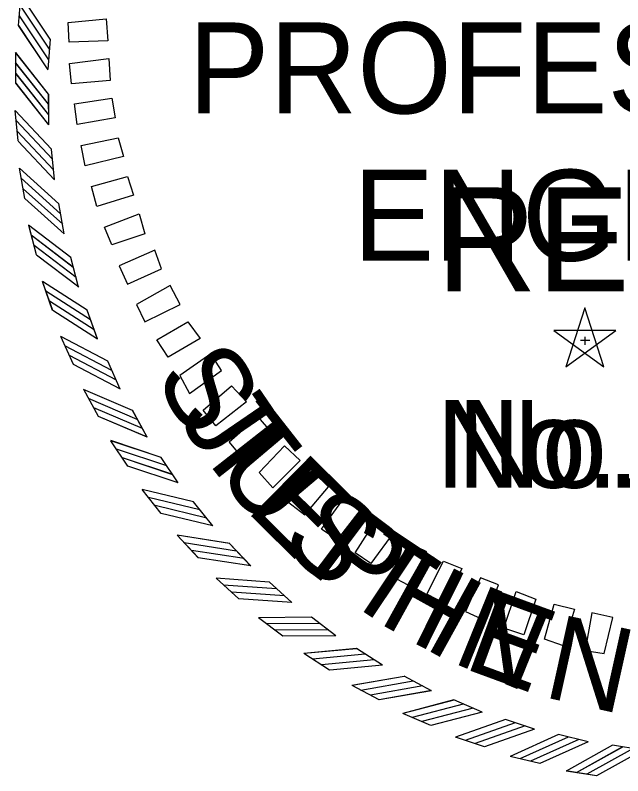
# Model space of a CAD drawing. Extents: x 16 to 1228740, y 11 to 152440.
# Drawn here: x 17.6793 to 17.754, y 10.8162 to 10.9098 of the extents above; entities that cross this region are included whole.
import ezdxf

# ---------------------------------------------------------------- set-up
doc = ezdxf.new("R2010")
doc.units = 0
for name, color, linetype in [('STAMP_FRED', 7, 'Continuous'), ('STAMP_JUSTIN', 7, 'Continuous'), ('STAMP_PRELIM', 7, 'Continuous')]:
    doc.layers.add(name, color=color, linetype=linetype)

msp = doc.modelspace()

# ---------------------------------------------------------------- linework, layer by layer
at = {"layer": 'STAMP_FRED'}
for p, q in [((17.6797, 10.908524), (17.679977, 10.912284)), ((17.683323, 10.903099), (17.683601, 10.906868)), ((17.67937, 10.901425), (17.679335, 10.905195)), ((17.683429, 10.896318), (17.683394, 10.900096)), ((17.679627, 10.894324), (17.679282, 10.898078)), ((17.684094, 10.889569), (17.683748, 10.893331)), ((17.680471, 10.887267), (17.679816, 10.89098)), ((17.685315, 10.882897), (17.684658, 10.886619)), ((17.681893, 10.880305), (17.680934, 10.883951)), ((17.687082, 10.87635), (17.686121, 10.880004)), ((17.683886, 10.873483), (17.682629, 10.877038)), ((17.749354, 10.873788), (17.746995, 10.866552)), ((17.751704, 10.866556), (17.749359, 10.873797)), ((17.689384, 10.86997), (17.688124, 10.873533)), ((17.753156, 10.871026), (17.745545, 10.871033)), ((17.745552, 10.871026), (17.751705, 10.866547)), ((17.747004, 10.866556), (17.753165, 10.871024)), ((17.686436, 10.86685), (17.68489, 10.870288)), ((17.749361, 10.870216), (17.749361, 10.869262)), ((17.748812, 10.86981), (17.749943, 10.86981)), ((17.692204, 10.863803), (17.690655, 10.867249)), ((17.689524, 10.86045), (17.6877, 10.863749)), ((17.695525, 10.857889), (17.693696, 10.861196)), ((17.693131, 10.854326), (17.69104, 10.857463)), ((17.699322, 10.85227), (17.697227, 10.855415)), ((17.697231, 10.848522), (17.694888, 10.851475)), ((17.703571, 10.846984), (17.701223, 10.849945)), ((17.701796, 10.843075), (17.699217, 10.845825)), ((17.708241, 10.842067), (17.705657, 10.844823)), ((17.706795, 10.838025), (17.703998, 10.840552)), ((17.713302, 10.837552), (17.710498, 10.840085)), ((17.712195, 10.833404), (17.709198, 10.835692)), ((17.718718, 10.83347), (17.715715, 10.835764)), ((17.724453, 10.82985), (17.721271, 10.831887)), ((17.717957, 10.829245), (17.714782, 10.831278)), ((17.730467, 10.826715), (17.727127, 10.828483)), ((17.724043, 10.825577), (17.720711, 10.82734)), ((17.736719, 10.824088), (17.733245, 10.825574)), ((17.730412, 10.822423), (17.726946, 10.823905)), ((17.743167, 10.821986), (17.739582, 10.82318)), ((17.749767, 10.820424), (17.746096, 10.821318)), ((17.737019, 10.819806), (17.733442, 10.820997)), ((17.756473, 10.819412), (17.75274, 10.82)), ((17.743819, 10.817743), (17.740156, 10.818635)), ((17.750767, 10.81625), (17.747043, 10.816836))]:
    msp.add_line(p, q, dxfattribs=at)
for points in [[(17.683598, 10.906863), (17.679974, 10.912288)], [(17.683494, 10.905612), (17.679871, 10.911036)], [(17.683427, 10.904304), (17.679803, 10.909728)], [(17.683326, 10.903094), (17.679703, 10.908519)], [(17.683392, 10.900092), (17.679333, 10.905199)], [(17.683392, 10.898836), (17.679333, 10.903943)], [(17.683433, 10.897527), (17.679374, 10.902633)], [(17.683433, 10.896313), (17.679374, 10.90142)], [(17.683745, 10.893327), (17.679279, 10.898081)], [(17.683849, 10.892075), (17.679382, 10.896829)], [(17.683998, 10.890774), (17.679531, 10.895528)], [(17.684098, 10.889565), (17.679632, 10.894319)], [(17.684657, 10.886614), (17.679813, 10.890983)], [(17.684863, 10.885375), (17.680019, 10.889744)], [(17.685119, 10.884091), (17.680275, 10.888459)], [(17.685319, 10.882894), (17.680475, 10.887263)], [(17.686119, 10.879999), (17.680931, 10.883953)], [(17.686427, 10.878782), (17.681239, 10.882736)], [(17.686789, 10.877523), (17.6816, 10.881477)], [(17.687086, 10.876346), (17.681898, 10.8803)], [(17.688123, 10.873528), (17.682626, 10.87704)], [(17.688531, 10.87234), (17.683034, 10.875852)], [(17.688995, 10.871115), (17.683497, 10.874627)], [(17.689389, 10.869967), (17.683891, 10.873479)], [(17.690654, 10.867244), (17.684886, 10.87029)], [(17.691159, 10.866094), (17.68539, 10.86914)], [(17.691722, 10.864912), (17.685954, 10.867958)], [(17.69221, 10.8638), (17.686441, 10.866846)], [(17.693696, 10.861191), (17.687696, 10.86375)], [(17.694293, 10.860086), (17.688293, 10.862646)], [(17.694953, 10.858954), (17.688953, 10.861514)], [(17.69553, 10.857887), (17.68953, 10.860447)], [(17.697227, 10.855409), (17.691036, 10.857465)], [(17.697914, 10.854358), (17.691723, 10.856413)], [(17.698664, 10.853284), (17.692473, 10.85534)], [(17.699328, 10.852269), (17.693137, 10.854324)], [(17.701223, 10.849939), (17.694884, 10.851476)], [(17.701995, 10.848948), (17.695655, 10.850485)], [(17.702831, 10.84794), (17.696492, 10.849477)], [(17.703576, 10.846983), (17.697237, 10.84852)], [(17.705658, 10.844818), (17.699213, 10.845826)], [(17.706508, 10.843894), (17.700063, 10.844902)], [(17.707425, 10.842959), (17.70098, 10.843967)], [(17.708247, 10.842066), (17.701802, 10.843074)], [(17.7105, 10.84008), (17.703994, 10.840553)], [(17.711424, 10.83923), (17.704918, 10.839702)], [(17.712415, 10.838373), (17.705909, 10.838846)], [(17.713308, 10.837551), (17.706802, 10.838024)], [(17.715717, 10.835759), (17.709194, 10.835692)], [(17.716708, 10.834987), (17.710185, 10.834921)], [(17.717766, 10.834216), (17.711243, 10.834149)], [(17.718724, 10.83347), (17.712201, 10.833404)], [(17.721273, 10.831883), (17.714778, 10.831278)], [(17.722324, 10.831196), (17.715829, 10.830591)], [(17.723443, 10.830514), (17.716948, 10.829909)], [(17.724459, 10.82985), (17.717964, 10.829245)], [(17.72713, 10.828479), (17.720707, 10.827339)], [(17.728235, 10.827881), (17.721812, 10.826742)], [(17.729406, 10.827294), (17.722983, 10.826155)], [(17.730473, 10.826716), (17.72405, 10.825577)], [(17.733248, 10.82557), (17.726941, 10.823904)], [(17.734398, 10.825065), (17.728091, 10.8234)], [(17.735614, 10.824577), (17.729307, 10.822911)], [(17.736725, 10.82409), (17.730418, 10.822424)], [(17.739586, 10.823176), (17.733438, 10.820996)], [(17.740774, 10.822769), (17.734626, 10.820588)], [(17.742025, 10.822382), (17.735877, 10.820201)], [(17.743173, 10.821988), (17.737025, 10.819807)], [(17.746099, 10.821314), (17.740152, 10.818633)], [(17.747317, 10.821006), (17.74137, 10.818325)], [(17.748596, 10.820724), (17.742649, 10.818043)], [(17.749772, 10.820427), (17.743826, 10.817746)], [(17.752744, 10.819997), (17.747039, 10.816834)], [(17.753983, 10.81979), (17.748278, 10.816627)], [(17.755281, 10.819615), (17.749576, 10.816452)], [(17.756478, 10.819415), (17.750773, 10.816252)]]:
    msp.add_lwpolyline(points, dxfattribs=at)
at = {"layer": 'STAMP_JUSTIN'}
for p, q in [((17.679702, 10.908525), (17.679979, 10.912285)), ((17.683325, 10.9031), (17.683602, 10.906868)), ((17.679372, 10.901426), (17.679337, 10.905196)), ((17.683431, 10.896319), (17.683396, 10.900097)), ((17.679629, 10.894325), (17.679283, 10.898079)), ((17.684096, 10.88957), (17.683749, 10.893333)), ((17.680472, 10.887269), (17.679818, 10.890981)), ((17.685316, 10.882899), (17.68466, 10.88662)), ((17.681895, 10.880306), (17.680936, 10.883952)), ((17.687084, 10.876351), (17.686122, 10.880006)), ((17.683888, 10.873485), (17.682631, 10.877039)), ((17.749354, 10.87379), (17.746995, 10.866554)), ((17.751704, 10.866558), (17.749359, 10.873798)), ((17.689385, 10.869972), (17.688126, 10.873535)), ((17.753156, 10.871028), (17.745545, 10.871035)), ((17.745552, 10.871028), (17.751705, 10.866548)), ((17.747004, 10.866558), (17.753165, 10.871025)), ((17.686437, 10.866852), (17.684891, 10.87029)), ((17.749361, 10.870218), (17.749361, 10.869263)), ((17.748812, 10.869812), (17.749943, 10.869812)), ((17.692206, 10.863805), (17.690656, 10.867251)), ((17.689526, 10.860452), (17.687701, 10.86375)), ((17.695526, 10.857891), (17.693697, 10.861198)), ((17.693132, 10.854328), (17.691042, 10.857465)), ((17.699324, 10.852273), (17.697228, 10.855417)), ((17.697232, 10.848524), (17.694889, 10.851477)), ((17.703572, 10.846986), (17.701224, 10.849947)), ((17.701797, 10.843078), (17.699219, 10.845828)), ((17.708243, 10.842069), (17.705658, 10.844825)), ((17.706796, 10.838027), (17.704, 10.840555)), ((17.713303, 10.837554), (17.7105, 10.840088)), ((17.712196, 10.833407), (17.7092, 10.835695)), ((17.718719, 10.833473), (17.715716, 10.835766)), ((17.724454, 10.829852), (17.721271, 10.83189)), ((17.717958, 10.829248), (17.714783, 10.831281)), ((17.730468, 10.826718), (17.727128, 10.828486)), ((17.724044, 10.825579), (17.720712, 10.827343)), ((17.73672, 10.824091), (17.733246, 10.825577)), ((17.730412, 10.822426), (17.726946, 10.823908)), ((17.743168, 10.821989), (17.739583, 10.823183)), ((17.749767, 10.820427), (17.746096, 10.821321)), ((17.737019, 10.819809), (17.733443, 10.821)), ((17.756473, 10.819415), (17.75274, 10.820003)), ((17.74382, 10.817746), (17.740157, 10.818638)), ((17.750767, 10.816252), (17.747043, 10.816839))]:
    msp.add_line(p, q, dxfattribs=at)
for points in [[(17.683599, 10.906864), (17.679976, 10.912288)], [(17.683496, 10.905613), (17.679872, 10.911037)], [(17.683428, 10.904304), (17.679805, 10.909729)], [(17.683328, 10.903095), (17.679705, 10.908519)], [(17.683393, 10.900093), (17.679335, 10.9052)], [(17.683393, 10.898837), (17.679335, 10.903944)], [(17.683434, 10.897528), (17.679376, 10.902634)], [(17.683434, 10.896314), (17.679376, 10.901421)], [(17.683747, 10.893328), (17.67928, 10.898082)], [(17.683851, 10.892076), (17.679384, 10.89683)], [(17.684, 10.890775), (17.679533, 10.895529)], [(17.6841, 10.889566), (17.679633, 10.89432)], [(17.684658, 10.886615), (17.679814, 10.890984)], [(17.684865, 10.885376), (17.680021, 10.889745)], [(17.685121, 10.884092), (17.680277, 10.888461)], [(17.685321, 10.882895), (17.680477, 10.887264)], [(17.686121, 10.880001), (17.680933, 10.883955)], [(17.686429, 10.878783), (17.681241, 10.882737)], [(17.68679, 10.877524), (17.681602, 10.881478)], [(17.687088, 10.876348), (17.6819, 10.880302)], [(17.688125, 10.87353), (17.682628, 10.877041)], [(17.688532, 10.872342), (17.683035, 10.875854)], [(17.688996, 10.871117), (17.683499, 10.874629)], [(17.68939, 10.869969), (17.683893, 10.873481)], [(17.690656, 10.867246), (17.684888, 10.870292)], [(17.69116, 10.866096), (17.685392, 10.869142)], [(17.691724, 10.864913), (17.685956, 10.867959)], [(17.692211, 10.863802), (17.686443, 10.866848)], [(17.693697, 10.861193), (17.687697, 10.863752)], [(17.694295, 10.860088), (17.688295, 10.862648)], [(17.694954, 10.858956), (17.688954, 10.861516)], [(17.695532, 10.857889), (17.689532, 10.860449)], [(17.697228, 10.855412), (17.691037, 10.857467)], [(17.697915, 10.85436), (17.691724, 10.856415)], [(17.698666, 10.853287), (17.692475, 10.855342)], [(17.699329, 10.852271), (17.693138, 10.854326)], [(17.701225, 10.849942), (17.694885, 10.851478)], [(17.701996, 10.848951), (17.695656, 10.850487)], [(17.702832, 10.847943), (17.696493, 10.849479)], [(17.703578, 10.846985), (17.697238, 10.848522)], [(17.705659, 10.84482), (17.699214, 10.845828)], [(17.70651, 10.843896), (17.700065, 10.844904)], [(17.707426, 10.842961), (17.700982, 10.843969)], [(17.708248, 10.842068), (17.701804, 10.843076)], [(17.710501, 10.840083), (17.703995, 10.840555)], [(17.711425, 10.839232), (17.704919, 10.839705)], [(17.712416, 10.838376), (17.70591, 10.838848)], [(17.713309, 10.837554), (17.706803, 10.838026)], [(17.715718, 10.835761), (17.709195, 10.835695)], [(17.716709, 10.83499), (17.710186, 10.834923)], [(17.717767, 10.834218), (17.711245, 10.834152)], [(17.718725, 10.833473), (17.712202, 10.833406)], [(17.721274, 10.831885), (17.714779, 10.83128)], [(17.722325, 10.831198), (17.71583, 10.830593)], [(17.723444, 10.830517), (17.716949, 10.829912)], [(17.724459, 10.829853), (17.717964, 10.829248)], [(17.727131, 10.828481), (17.720708, 10.827342)], [(17.728235, 10.827884), (17.721812, 10.826744)], [(17.729406, 10.827297), (17.722983, 10.826157)], [(17.730473, 10.826719), (17.724051, 10.82558)], [(17.733249, 10.825573), (17.726942, 10.823907)], [(17.734399, 10.825068), (17.728092, 10.823403)], [(17.735614, 10.82458), (17.729308, 10.822914)], [(17.736726, 10.824092), (17.730419, 10.822427)], [(17.739586, 10.823179), (17.733438, 10.820998)], [(17.740774, 10.822771), (17.734626, 10.820591)], [(17.742026, 10.822385), (17.735878, 10.820204)], [(17.743173, 10.821991), (17.737026, 10.81981)], [(17.7461, 10.821317), (17.740153, 10.818636)], [(17.747317, 10.821009), (17.74137, 10.818328)], [(17.748596, 10.820727), (17.74265, 10.818046)], [(17.749772, 10.820429), (17.743826, 10.817748)], [(17.752744, 10.82), (17.747039, 10.816837)], [(17.753983, 10.819793), (17.748278, 10.81663)], [(17.755281, 10.819618), (17.749576, 10.816455)], [(17.756478, 10.819418), (17.750773, 10.816255)]]:
    msp.add_lwpolyline(points, dxfattribs=at)
at = {"layer": 'STAMP_PRELIM'}
for p, q in [((17.685777, 10.908908), (17.69046, 10.90935)), ((17.69046, 10.90935), (17.690652, 10.906658)), ((17.685902, 10.906475), (17.685777, 10.908908)), ((17.690652, 10.906658), (17.685902, 10.906475)), ((17.68596, 10.90385), (17.690777, 10.904475)), ((17.68621, 10.90135), (17.68596, 10.90385)), ((17.690777, 10.904475), (17.69096, 10.901783)), ((17.69096, 10.901783), (17.68621, 10.90135)), ((17.686585, 10.898908), (17.691152, 10.8996)), ((17.691152, 10.8996), (17.691585, 10.897158)), ((17.686902, 10.89635), (17.686585, 10.898908)), ((17.691585, 10.897158), (17.686902, 10.89635)), ((17.687402, 10.893783), (17.69196, 10.894725)), ((17.69196, 10.894725), (17.692585, 10.892408)), ((17.687902, 10.891283), (17.687402, 10.893783)), ((17.692585, 10.892408), (17.687902, 10.891283)), ((17.688652, 10.888725), (17.693085, 10.889975)), ((17.693085, 10.889975), (17.693835, 10.887658)), ((17.689335, 10.886283), (17.688652, 10.888725)), ((17.693835, 10.887658), (17.689335, 10.886283)), ((17.690277, 10.883725), (17.694527, 10.88535)), ((17.694527, 10.88535), (17.69521, 10.882908)), ((17.691152, 10.881533), (17.690277, 10.883725)), ((17.69521, 10.882908), (17.691152, 10.881533)), ((17.69646, 10.880908), (17.692085, 10.878975)), ((17.697277, 10.8786), (17.69646, 10.880908)), ((17.692085, 10.878975), (17.693085, 10.876725)), ((17.693085, 10.876725), (17.697277, 10.8786)), ((17.698335, 10.876533), (17.69421, 10.874225)), ((17.699585, 10.874225), (17.698335, 10.876533)), ((17.69421, 10.874225), (17.69521, 10.8721)), ((17.69521, 10.8721), (17.699585, 10.874225)), ((17.69671, 10.86985), (17.700527, 10.8721)), ((17.700527, 10.8721), (17.702027, 10.870033)), ((17.702027, 10.870033), (17.698085, 10.867725)), ((17.698085, 10.867725), (17.69671, 10.86985)), ((17.703335, 10.868158), (17.699527, 10.865475)), ((17.704652, 10.8661), (17.703335, 10.868158)), ((17.699527, 10.865475), (17.70071, 10.863283)), ((17.70071, 10.863283), (17.704652, 10.8661)), ((17.702402, 10.861225), (17.705902, 10.864225)), ((17.705902, 10.864225), (17.70771, 10.862225)), ((17.70771, 10.862225), (17.70396, 10.859283)), ((17.70396, 10.859283), (17.702402, 10.861225)), ((17.709152, 10.860408), (17.705585, 10.857283)), ((17.710777, 10.858533), (17.709152, 10.860408)), ((17.70721, 10.85535), (17.710777, 10.858533)), ((17.705585, 10.857283), (17.70721, 10.85535)), ((17.709277, 10.853533), (17.712402, 10.85685)), ((17.712402, 10.85685), (17.714335, 10.855033)), ((17.714335, 10.855033), (17.71096, 10.851658)), ((17.71096, 10.851658), (17.709277, 10.853533)), ((17.716027, 10.853533), (17.712777, 10.849975)), ((17.717835, 10.851783), (17.716027, 10.853533)), ((17.714902, 10.84835), (17.717835, 10.851783)), ((17.71696, 10.8466), (17.719777, 10.850475)), ((17.719777, 10.850475), (17.72171, 10.848908)), ((17.712777, 10.849975), (17.714902, 10.84835)), ((17.72171, 10.848908), (17.718902, 10.845283)), ((17.721085, 10.843658), (17.723652, 10.847658)), ((17.723652, 10.847658), (17.725835, 10.846225)), ((17.718902, 10.845283), (17.71696, 10.8466)), ((17.725835, 10.846225), (17.723027, 10.84235)), ((17.72771, 10.84485), (17.725585, 10.840783)), ((17.729902, 10.843783), (17.72771, 10.84485)), ((17.727585, 10.839725), (17.729902, 10.843783)), ((17.723027, 10.84235), (17.721085, 10.843658)), ((17.729902, 10.8386), (17.73196, 10.842658)), ((17.73196, 10.842658), (17.73421, 10.841725)), ((17.73421, 10.841725), (17.732277, 10.83735)), ((17.725585, 10.840783), (17.727585, 10.839725)), ((17.736527, 10.8406), (17.734652, 10.836475)), ((17.73871, 10.839725), (17.736527, 10.8406)), ((17.737085, 10.83535), (17.73871, 10.839725)), ((17.732277, 10.83735), (17.729902, 10.8386)), ((17.739402, 10.834408), (17.740902, 10.838908)), ((17.740902, 10.838908), (17.743335, 10.837975)), ((17.743335, 10.837975), (17.741835, 10.8336)), ((17.744402, 10.833033), (17.745585, 10.83735)), ((17.745585, 10.83735), (17.748085, 10.836725)), ((17.734652, 10.836475), (17.737085, 10.83535)), ((17.748085, 10.836725), (17.74671, 10.832225)), ((17.75021, 10.836283), (17.749402, 10.831658)), ((17.752777, 10.835725), (17.75021, 10.836283)), ((17.75171, 10.831283), (17.752777, 10.835725)), ((17.741835, 10.8336), (17.739402, 10.834408)), ((17.74671, 10.832225), (17.744402, 10.833033)), ((17.749402, 10.831658), (17.75171, 10.831283))]:
    msp.add_line(p, q, dxfattribs=at)

# ---------------------------------------------------------------- texts
at = {"layer": 'STAMP_FRED'}
for s, height, p in [('PROFESSIONAL', 0.01119382, (17.700561, 10.897711)), ('ENGINEER', 0.0111938, (17.720817, 10.879588)), ('No.14501', 0.010794, (17.733619, 10.851677))]:
    msp.add_text(s, height=height, dxfattribs=at).set_placement(p)
for s, rotation, p in [('S', 300.79847, (17.696258, 10.865347)), ('T', 308.09448, (17.701345, 10.856814)), ('E', 315.39049, (17.707475, 10.848997)), ('P', 323.0513, (17.714924, 10.841696)), ('H', 331.07691, (17.723698, 10.835185)), ('E', 339.83212, (17.734202, 10.829556)), ('N', 347.49293, (17.744004, 10.825992))]:
    msp.add_text(s, height=0.010417, rotation=rotation, dxfattribs=at).set_placement(p)
at = {"layer": 'STAMP_JUSTIN'}
for s, height, p in [('PROFESSIONAL', 0.01119355, (17.700563, 10.897712)), ('ENGINEER', 0.0111936, (17.720818, 10.879589)), ('No.18018', 0.0107938, (17.731051, 10.851679))]:
    msp.add_text(s, height=height, dxfattribs=at).set_placement(p)
for s, rotation, p in [('J', 304.36793, (17.699173, 10.860274)), ('U', 310.20474, (17.703657, 10.853718)), ('S', 318.95995, (17.711573, 10.844822)), ('T', 326.25596, (17.719143, 10.838401)), ('I', 333.55197, (17.727467, 10.832993)), ('N', 337.92957, (17.732768, 10.830271))]:
    msp.add_text(s, height=0.010416, rotation=rotation, dxfattribs=at).set_placement(p)
at = {"layer": 'STAMP_PRELIM'}
msp.add_text('REVISION', height=0.0127938, dxfattribs=at).set_placement((17.731085, 10.87585))

doc.saveas('drawing.dxf')
